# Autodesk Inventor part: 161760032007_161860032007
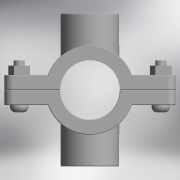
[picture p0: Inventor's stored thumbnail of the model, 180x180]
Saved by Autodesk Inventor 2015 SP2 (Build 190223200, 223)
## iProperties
Created: 2017-05
Part Number: 161760032007_161860032007
Material: Generic
Description: PLASSON DOUBLE SADDLE 32-3/4"
Document SubType Name: Modeling
Designer: KIM
Density: 1 g/cm^3
Appearance: Default
Author: KIM
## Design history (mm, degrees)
derived "16176.ipt"
feature "Solid1::16176.ipt"
feature "Solid2::16176.ipt"
tag "TaggingFeature1"
body "Solid1"
body "Solid2"
other parameters: "d0" = 48, "d1" = 92, "d2" = 16, "d3" = 32, "d5" = 0, "d6" = 4.6, "d7" = 92, "d8" = 0.1, "d10" = 0, "d11" = 0.32, "d20" = 0.32, "d23" = 0.32, "d37" = 8, "d38" = 24, "d39" = 0, "d40" = 3, "d41" = 5, "d42" = 0, "d43" = 6, "d44" = 3, "d45" = 0, "d46" = 0.32, "d52" = 24.117, "d53" = 19, "d54" = 0, "d55" = 19, "d57" = 0, "d58" = 34.56, "d60" = 0, "d66" = 0, "d67" = 82, "d68" = 31.3521, "d69" = 24.117, "d70" = 19, "d71" = 0, "d72" = 19, "d74" = 0, "d75" = 0.32, "d_" = 32, "B_" = 19, "G_" = 24.117, "A_" = 41, "L_" = 92, "l_2" = 19
